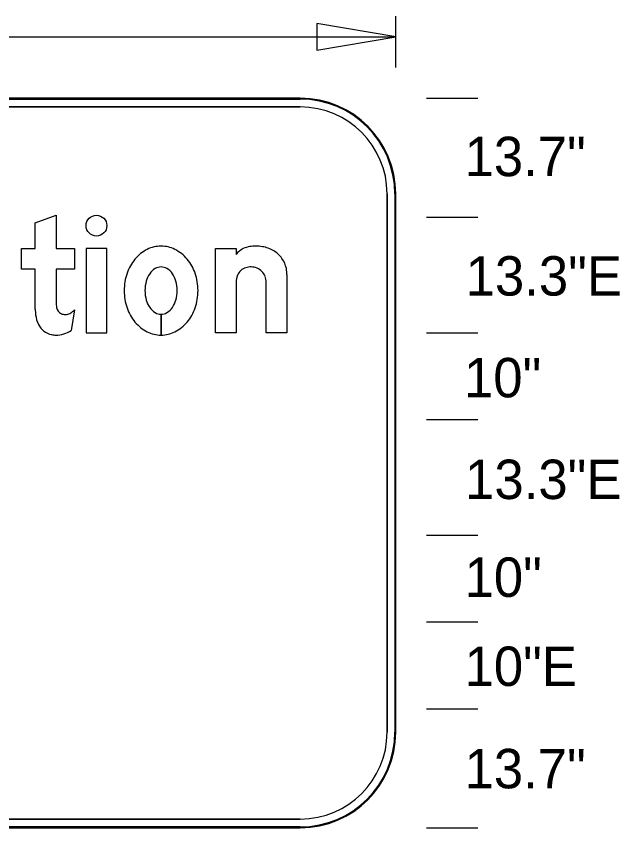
# Model space of a CAD drawing. Extents: x 0 to 770, y 0 to 495.
# Drawn here: x 707.7 to 761.3, y 402.6 to 474.6 of the extents above; entities that cross this region are included whole.
import ezdxf

# ---------------------------------------------------------------- set-up
doc = ezdxf.new("R2010")
doc.units = 0
for name, color, linetype in [('Default', 7, 'Continuous'), ('Dimension', 7, 'Continuous'), ('GSBWFill', 7, 'Continuous'), ('GSColorFill', 7, 'Continuous'), ('GSDims', 7, 'Continuous'), ('GSOutline', 7, 'Continuous')]:
    doc.layers.add(name, color=color, linetype=linetype)

msp = doc.modelspace()

# ---------------------------------------------------------------- linework, layer by layer
at = {"layer": 'Dimension'}
msp.add_lwpolyline([(741.425, 472.797), (734.408, 473.986), (734.408, 471.608)], close=True, dxfattribs=at)
at = {"layer": 'GSBWFill'}
for p, q in [((732.944, 467.333), (601.886, 467.333)), ((732.944, 467.333), (601.886, 467.333)), ((601.886, 466.562), (732.944, 466.562)), ((740.654, 458.853), (740.654, 411.055)), ((741.425, 411.055), (741.425, 458.853)), ((741.425, 411.055), (741.425, 458.853)), ((729.91, 446.518), (729.91, 450.995)), ((720.579, 448.158), (720.579, 446.313)), ((720.58, 446.313), (720.58, 448.158)), ((712.601, 446.708), (712.601, 446.708)), ((732.944, 403.346), (601.894, 403.346)), ((601.886, 402.575), (732.944, 402.575)), ((601.894, 402.575), (732.944, 402.575))]:
    msp.add_line(p, q, dxfattribs=at)
for points in [[(709.403, 448.611), (709.403, 452.157), (708.172, 452.157), (708.172, 454.003), (709.403, 454.003), (709.403, 456.276), (711.248, 456.951), (711.248, 454.003), (712.889, 454.003), (712.889, 452.157), (711.248, 452.157), (711.248, 449.26)], [(727.244, 450.995), (727.244, 446.518), (725.398, 446.518), (725.398, 454.003), (727.244, 454.003), (727.244, 453.479)], [(731.755, 451.662), (731.755, 446.518), (729.91, 446.518)], [(712.889, 448.543), (712.889, 448.543), (712.601, 446.708)]]:
    msp.add_lwpolyline(points, dxfattribs=at)
msp.add_lwpolyline([(715.76, 446.518), (715.76, 454.003), (713.914, 454.003), (713.914, 446.518)], close=True, dxfattribs=at)
for centre, radius, start, end in [((732.944, 458.853), 8.48, 0, 90), ((732.944, 458.853), 8.48, 0, 90), ((732.944, 458.853), 7.709, 0, 90), ((732.944, 411.055), 8.48, 270, 0), ((732.944, 411.055), 7.709, 270, 0), ((732.944, 411.055), 8.48, 270, 0)]:
    msp.add_arc(centre, radius, start, end, dxfattribs=at)
msp.add_ellipse((714.837, 456.028), major_axis=(0, 0.923), ratio=0.999978, dxfattribs=at)
for centre, major_axis, ratio, start_param, end_param in [((720.869, 450.882), (0, 3.394), 0.999998, 0.462327, 0.877337), ((720.579, 451.464), (0, 2.744), 0.999998, 0, 0.462327), ((720.579, 451.464), (0, 2.744), 0.999998, 5.820858, 6.283185), ((720.289, 450.882), (0, 3.394), 0.999998, 5.405848, 5.820858), ((728.624, 452.419), (0, 1.741), 0.999997, 0.444839, 0.915988), ((728.758, 452.14), (0, 2.051), 0.999997, 0.148374, 0.444839), ((728.994, 450.556), (0, 3.652), 0.999997, 0, 0.148374), ((728.994, 450.655), (0, 3.553), 0.999997, 6.11698, 6.283185), ((729.118, 451.339), (0, 2.858), 0.999997, 5.743536, 6.11991), ((729.337, 451.711), (0, 2.426), 0.999997, 5.331411, 5.742098), ((721.322, 450.506), (0, 3.983), 0.999998, 0.877337, 1.239225), ((719.836, 450.506), (0, 3.983), 0.999998, 5.04396, 5.405848), ((729.375, 451.746), (0, 2.374), 0.999997, 4.909454, 5.328907), ((722.035, 450.26), (0, 4.737), 0.999998, 1.239225, 1.570796), ((721.408, 450.487), (0, 2.233), 0.999998, 0.971621, 1.295121), ((720.9, 450.834), (0, 1.618), 0.999998, 0.545205, 0.971621), ((720.579, 451.363), (0, 0.999), 0.999998, 0, 0.545205), ((720.579, 451.363), (0, 0.999), 0.999998, 5.73798, 6.283185), ((720.258, 450.834), (0, 1.618), 0.999998, 5.311564, 5.73798), ((719.75, 450.487), (0, 2.233), 0.999998, 4.988064, 5.311564), ((719.123, 450.26), (0, 4.737), 0.999998, 4.712389, 5.04396), ((728.4, 451.221), (0, 1.115), 0.999997, 0.274492, 1.206206), ((728.577, 450.644), (0, 1.719), 0.999997, 0, 0.282279), ((728.577, 451.026), (0, 1.336), 0.999997, 5.879574, 6.283185), ((728.575, 451.033), (0, 1.331), 0.999997, 5.093345, 5.87639), ((728.813, 451.662), (0, 2.942), 0.999997, 4.712389, 4.900007), ((722.211, 450.26), (0, 3.067), 0.999998, 1.295121, 1.570796), ((718.947, 450.26), (0, 3.067), 0.999998, 4.712389, 4.988064), ((728.995, 450.995), (0, 1.751), 0.999997, 1.206869, 1.570796), ((728.486, 451.005), (0, 1.423), 0.999997, 4.705543, 5.088361), ((722.035, 450.26), (0, 4.737), 0.999998, 1.570796, 1.902368), ((722.211, 450.26), (0, 3.067), 0.999998, 1.570796, 1.846471), ((718.947, 450.26), (0, 3.067), 0.999998, 4.436714, 4.712389), ((719.123, 450.26), (0, 4.737), 0.999998, 4.380818, 4.712389), ((713.553, 449.26), (0, 2.304), 0.999989, 1.570796, 1.786412), ((721.408, 450.033), (0, 2.233), 0.999998, 1.846471, 2.169972), ((719.75, 450.033), (0, 2.233), 0.999998, 4.113214, 4.436714), ((713.415, 448.611), (0, 4.012), 0.999989, 1.570796, 1.696187), ((712.053, 448.898), (0, 0.763), 0.999989, 1.74402, 2.68798), ((712.062, 449.079), (0, 0.932), 0.999989, 2.764976, 3.141593), ((712.062, 449.454), (0, 1.307), 0.999989, 3.141593, 3.322793), ((712.098, 449.028), (0, 0.881), 0.999989, 3.369141, 3.829733), ((710.036, 451.663), (0, 4.228), 0.999989, 3.810579, 3.882326), ((721.322, 450.015), (0, 3.983), 0.999998, 1.902368, 2.264256), ((720.9, 449.686), (0, 1.618), 0.999998, 2.169972, 2.596388), ((720.579, 449.157), (0, 0.999), 0.999998, 2.596388, 3.141593), ((720.579, 449.157), (0, 0.999), 0.999998, 3.142106, 3.686798), ((720.258, 449.686), (0, 1.618), 0.999998, 3.686798, 4.113214), ((719.836, 450.015), (0, 3.983), 0.999998, 4.018929, 4.380818), ((712.064, 448.423), (0, 2.648), 0.999989, 1.689445, 2.022806), ((720.869, 449.638), (0, 3.394), 0.999998, 2.264256, 2.679265), ((720.289, 449.638), (0, 3.394), 0.999998, 3.60392, 4.018929), ((711.262, 448.038), (0, 1.759), 0.999989, 2.024831, 2.464069), ((710.771, 449.99), (0, 3.757), 0.999989, 3.455425, 3.650292), ((711.169, 447.958), (0, 1.639), 0.999989, 2.477712, 2.946815), ((711.234, 448.267), (0, 1.954), 0.999989, 2.944983, 3.141593), ((711.234, 448.713), (0, 2.4), 0.999989, 3.141593, 3.436283), ((720.579, 449.057), (0, 2.744), 0.999998, 2.679265, 3.141593), ((720.579, 449.057), (0, 2.744), 0.999998, 3.14178, 3.60392)]:
    msp.add_ellipse(centre, major_axis=major_axis, ratio=ratio, start_param=start_param, end_param=end_param, dxfattribs=at)
at = {"layer": 'GSColorFill'}
for p, q in [((732.944, 467.333), (601.886, 467.333)), ((732.944, 467.333), (601.886, 467.333)), ((732.944, 467.333), (601.886, 467.333)), ((601.886, 467.256), (732.944, 467.256)), ((601.886, 466.562), (732.944, 466.562)), ((740.654, 458.853), (740.654, 411.055)), ((741.348, 458.853), (741.348, 411.055)), ((741.425, 411.055), (741.425, 458.853)), ((741.425, 411.055), (741.425, 458.853)), ((741.425, 411.055), (741.425, 458.853)), ((729.91, 446.518), (729.91, 450.995)), ((720.579, 448.158), (720.579, 446.313)), ((720.58, 446.313), (720.58, 448.158)), ((712.601, 446.708), (712.601, 446.708)), ((732.944, 403.346), (601.894, 403.346)), ((601.886, 402.575), (732.944, 402.575)), ((732.944, 402.652), (601.887, 402.652)), ((601.887, 402.575), (732.944, 402.575)), ((601.894, 402.575), (732.944, 402.575))]:
    msp.add_line(p, q, dxfattribs=at)
for points in [[(709.403, 448.611), (709.403, 452.157), (708.172, 452.157), (708.172, 454.003), (709.403, 454.003), (709.403, 456.276), (711.248, 456.951), (711.248, 454.003), (712.889, 454.003), (712.889, 452.157), (711.248, 452.157), (711.248, 449.26)], [(727.244, 450.995), (727.244, 446.518), (725.398, 446.518), (725.398, 454.003), (727.244, 454.003), (727.244, 453.479)], [(731.755, 451.662), (731.755, 446.518), (729.91, 446.518)], [(712.889, 448.543), (712.889, 448.543), (712.601, 446.708)]]:
    msp.add_lwpolyline(points, dxfattribs=at)
msp.add_lwpolyline([(715.76, 446.518), (715.76, 454.003), (713.914, 454.003), (713.914, 446.518)], close=True, dxfattribs=at)
for centre, radius, start, end in [((732.944, 458.853), 8.48, 0, 90), ((732.944, 458.853), 8.48, 0, 90), ((732.944, 458.853), 8.48, 0, 90), ((732.944, 458.853), 8.403, 0, 90), ((732.944, 458.853), 7.709, 0, 90), ((732.944, 411.055), 8.48, 270, 0), ((732.944, 411.055), 8.48, 270, 0), ((732.944, 411.055), 7.709, 270, 0), ((732.944, 411.055), 8.48, 270, 0), ((732.944, 411.055), 8.403, 270, 0)]:
    msp.add_arc(centre, radius, start, end, dxfattribs=at)
msp.add_ellipse((714.837, 456.028), major_axis=(0, 0.923), ratio=0.999978, dxfattribs=at)
for centre, major_axis, ratio, start_param, end_param in [((720.869, 450.882), (0, 3.394), 0.999998, 0.462327, 0.877337), ((720.579, 451.464), (0, 2.744), 0.999998, 0, 0.462327), ((720.579, 451.464), (0, 2.744), 0.999998, 5.820858, 6.283185), ((720.289, 450.882), (0, 3.394), 0.999998, 5.405848, 5.820858), ((728.624, 452.419), (0, 1.741), 0.999997, 0.444839, 0.915988), ((728.758, 452.14), (0, 2.051), 0.999997, 0.148374, 0.444839), ((728.994, 450.556), (0, 3.652), 0.999997, 0, 0.148374), ((728.994, 450.655), (0, 3.553), 0.999997, 6.11698, 6.283185), ((729.118, 451.339), (0, 2.858), 0.999997, 5.743536, 6.11991), ((729.337, 451.711), (0, 2.426), 0.999997, 5.331411, 5.742098), ((721.322, 450.506), (0, 3.983), 0.999998, 0.877337, 1.239225), ((719.836, 450.506), (0, 3.983), 0.999998, 5.04396, 5.405848), ((729.375, 451.746), (0, 2.374), 0.999997, 4.909454, 5.328907), ((722.035, 450.26), (0, 4.737), 0.999998, 1.239225, 1.570796), ((721.408, 450.487), (0, 2.233), 0.999998, 0.971621, 1.295121), ((720.9, 450.834), (0, 1.618), 0.999998, 0.545205, 0.971621), ((720.579, 451.363), (0, 0.999), 0.999998, 0, 0.545205), ((720.579, 451.363), (0, 0.999), 0.999998, 5.73798, 6.283185), ((720.258, 450.834), (0, 1.618), 0.999998, 5.311564, 5.73798), ((719.75, 450.487), (0, 2.233), 0.999998, 4.988064, 5.311564), ((719.123, 450.26), (0, 4.737), 0.999998, 4.712389, 5.04396), ((728.4, 451.221), (0, 1.115), 0.999997, 0.274492, 1.206206), ((728.577, 450.644), (0, 1.719), 0.999997, 0, 0.282279), ((728.577, 451.026), (0, 1.336), 0.999997, 5.879574, 6.283185), ((728.575, 451.033), (0, 1.331), 0.999997, 5.093345, 5.87639), ((728.813, 451.662), (0, 2.942), 0.999997, 4.712389, 4.900007), ((722.211, 450.26), (0, 3.067), 0.999998, 1.295121, 1.570796), ((718.947, 450.26), (0, 3.067), 0.999998, 4.712389, 4.988064), ((728.995, 450.995), (0, 1.751), 0.999997, 1.206869, 1.570796), ((728.486, 451.005), (0, 1.423), 0.999997, 4.705543, 5.088361), ((722.035, 450.26), (0, 4.737), 0.999998, 1.570796, 1.902368), ((722.211, 450.26), (0, 3.067), 0.999998, 1.570796, 1.846471), ((718.947, 450.26), (0, 3.067), 0.999998, 4.436714, 4.712389), ((719.123, 450.26), (0, 4.737), 0.999998, 4.380818, 4.712389), ((713.553, 449.26), (0, 2.304), 0.999989, 1.570796, 1.786412), ((721.408, 450.033), (0, 2.233), 0.999998, 1.846471, 2.169972), ((719.75, 450.033), (0, 2.233), 0.999998, 4.113214, 4.436714), ((713.415, 448.611), (0, 4.012), 0.999989, 1.570796, 1.696187), ((712.053, 448.898), (0, 0.763), 0.999989, 1.74402, 2.68798), ((712.062, 449.079), (0, 0.932), 0.999989, 2.764976, 3.141593), ((712.062, 449.454), (0, 1.307), 0.999989, 3.141593, 3.322793), ((712.098, 449.028), (0, 0.881), 0.999989, 3.369141, 3.829733), ((710.036, 451.663), (0, 4.228), 0.999989, 3.810579, 3.882326), ((721.322, 450.015), (0, 3.983), 0.999998, 1.902368, 2.264256), ((720.9, 449.686), (0, 1.618), 0.999998, 2.169972, 2.596388), ((720.579, 449.157), (0, 0.999), 0.999998, 2.596388, 3.141593), ((720.579, 449.157), (0, 0.999), 0.999998, 3.142106, 3.686798), ((720.258, 449.686), (0, 1.618), 0.999998, 3.686798, 4.113214), ((719.836, 450.015), (0, 3.983), 0.999998, 4.018929, 4.380818), ((712.064, 448.423), (0, 2.648), 0.999989, 1.689445, 2.022806), ((720.869, 449.638), (0, 3.394), 0.999998, 2.264256, 2.679265), ((720.289, 449.638), (0, 3.394), 0.999998, 3.60392, 4.018929), ((711.262, 448.038), (0, 1.759), 0.999989, 2.024831, 2.464069), ((710.771, 449.99), (0, 3.757), 0.999989, 3.455425, 3.650292), ((711.169, 447.958), (0, 1.639), 0.999989, 2.477712, 2.946815), ((711.234, 448.267), (0, 1.954), 0.999989, 2.944983, 3.141593), ((711.234, 448.713), (0, 2.4), 0.999989, 3.141593, 3.436283), ((720.579, 449.057), (0, 2.744), 0.999998, 2.679265, 3.141593), ((720.579, 449.057), (0, 2.744), 0.999998, 3.14178, 3.60392)]:
    msp.add_ellipse(centre, major_axis=major_axis, ratio=ratio, start_param=start_param, end_param=end_param, dxfattribs=at)
at = {"layer": 'GSDims'}
for p, q in [((741.425, 470.065), (741.425, 474.618)), ((593.406, 472.797), (741.425, 472.797)), ((744.157, 467.333), (748.71, 467.333)), ((744.157, 456.771), (748.71, 456.771)), ((744.157, 456.771), (748.71, 456.771)), ((744.157, 446.518), (748.71, 446.518)), ((744.157, 446.518), (748.71, 446.518)), ((744.157, 438.808), (748.71, 438.808)), ((744.157, 438.808), (748.71, 438.808)), ((744.157, 428.555), (748.71, 428.555)), ((744.157, 428.555), (748.71, 428.555)), ((744.157, 420.846), (748.71, 420.846)), ((744.157, 420.846), (748.71, 420.846)), ((744.157, 413.136), (748.71, 413.136)), ((744.157, 413.136), (748.71, 413.136)), ((744.157, 402.575), (748.71, 402.575))]:
    msp.add_line(p, q, dxfattribs=at)
at = {"layer": 'GSOutline'}
for p, q in [((732.944, 467.333), (601.886, 467.333)), ((732.944, 467.333), (601.886, 467.333)), ((732.944, 466.562), (601.886, 466.562)), ((740.654, 411.055), (740.654, 458.853)), ((741.425, 411.055), (741.425, 458.853)), ((741.425, 411.055), (741.425, 458.853)), ((729.91, 446.518), (729.91, 450.995)), ((712.601, 446.708), (712.601, 446.708)), ((601.886, 403.346), (732.944, 403.346)), ((601.886, 402.575), (732.944, 402.575)), ((601.886, 402.575), (732.944, 402.575))]:
    msp.add_line(p, q, dxfattribs=at)
for points in [[(709.403, 448.611), (709.403, 452.157), (708.172, 452.157), (708.172, 454.003), (709.403, 454.003), (709.403, 456.276), (711.248, 456.951), (711.248, 454.003), (712.889, 454.003), (712.889, 452.157), (711.248, 452.157), (711.248, 449.26)], [(727.244, 450.995), (727.244, 446.518), (725.398, 446.518), (725.398, 454.003), (727.244, 454.003), (727.244, 453.479)], [(731.755, 451.662), (731.755, 446.518), (729.91, 446.518)], [(712.889, 448.543), (712.889, 448.543), (712.601, 446.708)]]:
    msp.add_lwpolyline(points, dxfattribs=at)
msp.add_lwpolyline([(715.76, 446.518), (715.76, 454.003), (713.914, 454.003), (713.914, 446.518)], close=True, dxfattribs=at)
for centre, radius, start, end in [((732.944, 458.853), 8.48, 0, 90), ((732.944, 458.853), 8.48, 0, 90), ((732.944, 458.853), 7.709, 0, 90), ((732.944, 411.055), 8.48, 270, 0), ((732.944, 411.055), 7.709, 270, 0), ((732.944, 411.055), 8.48, 270, 0)]:
    msp.add_arc(centre, radius, start, end, dxfattribs=at)
msp.add_ellipse((714.837, 456.028), major_axis=(0, 0.923), ratio=0.999978, dxfattribs=at)
for centre, major_axis, ratio, start_param, end_param in [((720.869, 450.882), (0, 3.394), 0.999998, 0.462327, 0.877337), ((720.579, 451.464), (0, 2.744), 0.999998, 0, 0.462327), ((720.579, 451.464), (0, 2.744), 0.999998, 5.820858, 6.283185), ((720.289, 450.882), (0, 3.394), 0.999998, 5.405848, 5.820858), ((728.624, 452.419), (0, 1.741), 0.999997, 0.444839, 0.915988), ((728.758, 452.14), (0, 2.051), 0.999997, 0.148374, 0.444839), ((728.994, 450.556), (0, 3.652), 0.999997, 0, 0.148374), ((728.994, 450.655), (0, 3.553), 0.999997, 6.11698, 6.283185), ((729.118, 451.339), (0, 2.858), 0.999997, 5.743536, 6.11991), ((729.337, 451.711), (0, 2.426), 0.999997, 5.331411, 5.742098), ((721.322, 450.506), (0, 3.983), 0.999998, 0.877337, 1.239225), ((719.836, 450.506), (0, 3.983), 0.999998, 5.04396, 5.405848), ((729.375, 451.746), (0, 2.374), 0.999997, 4.909454, 5.328907), ((722.035, 450.26), (0, 4.737), 0.999998, 1.239225, 1.570796), ((721.408, 450.487), (0, 2.233), 0.999998, 0.971621, 1.295121), ((720.9, 450.834), (0, 1.618), 0.999998, 0.545205, 0.971621), ((720.579, 451.363), (0, 0.999), 0.999998, 0, 0.545205), ((720.579, 451.363), (0, 0.999), 0.999998, 5.73798, 6.283185), ((720.258, 450.834), (0, 1.618), 0.999998, 5.311564, 5.73798), ((719.75, 450.487), (0, 2.233), 0.999998, 4.988064, 5.311564), ((719.123, 450.26), (0, 4.737), 0.999998, 4.712389, 5.04396), ((728.4, 451.221), (0, 1.115), 0.999997, 0.274492, 1.206206), ((728.577, 450.644), (0, 1.719), 0.999997, 0, 0.282279), ((728.577, 451.026), (0, 1.336), 0.999997, 5.879574, 6.283185), ((728.575, 451.033), (0, 1.331), 0.999997, 5.093345, 5.87639), ((728.813, 451.662), (0, 2.942), 0.999997, 4.712389, 4.900007), ((722.211, 450.26), (0, 3.067), 0.999998, 1.295121, 1.570796), ((718.947, 450.26), (0, 3.067), 0.999998, 4.712389, 4.988064), ((728.995, 450.995), (0, 1.751), 0.999997, 1.206869, 1.570796), ((728.486, 451.005), (0, 1.423), 0.999997, 4.705543, 5.088361), ((722.035, 450.26), (0, 4.737), 0.999998, 1.570796, 1.902368), ((722.211, 450.26), (0, 3.067), 0.999998, 1.570796, 1.846471), ((718.947, 450.26), (0, 3.067), 0.999998, 4.436714, 4.712389), ((719.123, 450.26), (0, 4.737), 0.999998, 4.380818, 4.712389), ((713.553, 449.26), (0, 2.304), 0.999989, 1.570796, 1.786412), ((721.408, 450.033), (0, 2.233), 0.999998, 1.846471, 2.169972), ((719.75, 450.033), (0, 2.233), 0.999998, 4.113214, 4.436714), ((713.415, 448.611), (0, 4.012), 0.999989, 1.570796, 1.696187), ((712.053, 448.898), (0, 0.763), 0.999989, 1.74402, 2.68798), ((712.062, 449.079), (0, 0.932), 0.999989, 2.764976, 3.141593), ((712.062, 449.454), (0, 1.307), 0.999989, 3.141593, 3.322793), ((712.098, 449.028), (0, 0.881), 0.999989, 3.369141, 3.829733), ((710.036, 451.663), (0, 4.228), 0.999989, 3.810579, 3.882326), ((721.322, 450.015), (0, 3.983), 0.999998, 1.902368, 2.264256), ((720.9, 449.686), (0, 1.618), 0.999998, 2.169972, 2.596388), ((720.579, 449.157), (0, 0.999), 0.999998, 2.596388, 3.141593), ((720.579, 449.157), (0, 0.999), 0.999998, 3.141593, 3.686798), ((720.258, 449.686), (0, 1.618), 0.999998, 3.686798, 4.113214), ((719.836, 450.015), (0, 3.983), 0.999998, 4.018929, 4.380818), ((712.064, 448.423), (0, 2.648), 0.999989, 1.689445, 2.022806), ((720.869, 449.638), (0, 3.394), 0.999998, 2.264256, 2.679265), ((720.289, 449.638), (0, 3.394), 0.999998, 3.60392, 4.018929), ((711.262, 448.038), (0, 1.759), 0.999989, 2.024831, 2.464069), ((710.771, 449.99), (0, 3.757), 0.999989, 3.455425, 3.650292), ((711.169, 447.958), (0, 1.639), 0.999989, 2.477712, 2.946815), ((711.234, 448.267), (0, 1.954), 0.999989, 2.944983, 3.141593), ((711.234, 448.713), (0, 2.4), 0.999989, 3.141593, 3.436283), ((720.579, 449.057), (0, 2.744), 0.999998, 2.679265, 3.141593), ((720.579, 449.057), (0, 2.744), 0.999998, 3.141593, 3.60392)]:
    msp.add_ellipse(centre, major_axis=major_axis, ratio=ratio, start_param=start_param, end_param=end_param, dxfattribs=at)

# ---------------------------------------------------------------- texts
at = {"layer": 'Default'}
for s, p in [('13.7"', (747.529, 460.421)), ('13.3"E', (747.628, 449.817)), ('10"', (747.48, 440.786)), ('13.3"E', (747.579, 431.756)), ('10"', (747.529, 423.07)), ('10"E', (747.529, 415.164)), ('13.7"', (747.529, 406.077))]:
    msp.add_text(s, height=3.5, dxfattribs=at).set_placement(p)

doc.saveas('drawing.dxf')
